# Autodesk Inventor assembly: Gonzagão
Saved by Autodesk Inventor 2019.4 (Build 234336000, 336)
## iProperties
Created: 2020-03
Part Number: Gonzagão
Document SubType Name: Assembly
Designer: Administrator
Title: Gonzagão v8
Author: Administrator
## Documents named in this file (4)
- c:\worker\convert-fusion-r02\tmp\job-1\20\output\files\efe7eb1f-ec52-4416-b2d1-b8aaea3c85fa\07dbc19a-80da-4357-b0b1-e46c443ff96c.iam
- c:\worker\convert-fusion-r02\tmp\job-1\20\output\files\efe7eb1f-ec52-4416-b2d1-b8aaea3c85fa\Parafuso M3 x 12 (3).ipt
- c:\worker\convert-fusion-r02\tmp\job-1\20\output\files\efe7eb1f-ec52-4416-b2d1-b8aaea3c85fa\Castanha.ipt
- c:\worker\convert-fusion-r02\tmp\job-1\20\output\files\efe7eb1f-ec52-4416-b2d1-b8aaea3c85fa\Gonzagão v8.ipt
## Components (3 placed, 3 different names)
1. Parafuso M3 x 12 (3):1
2. Castanha:1
3. Gonzagão v8
